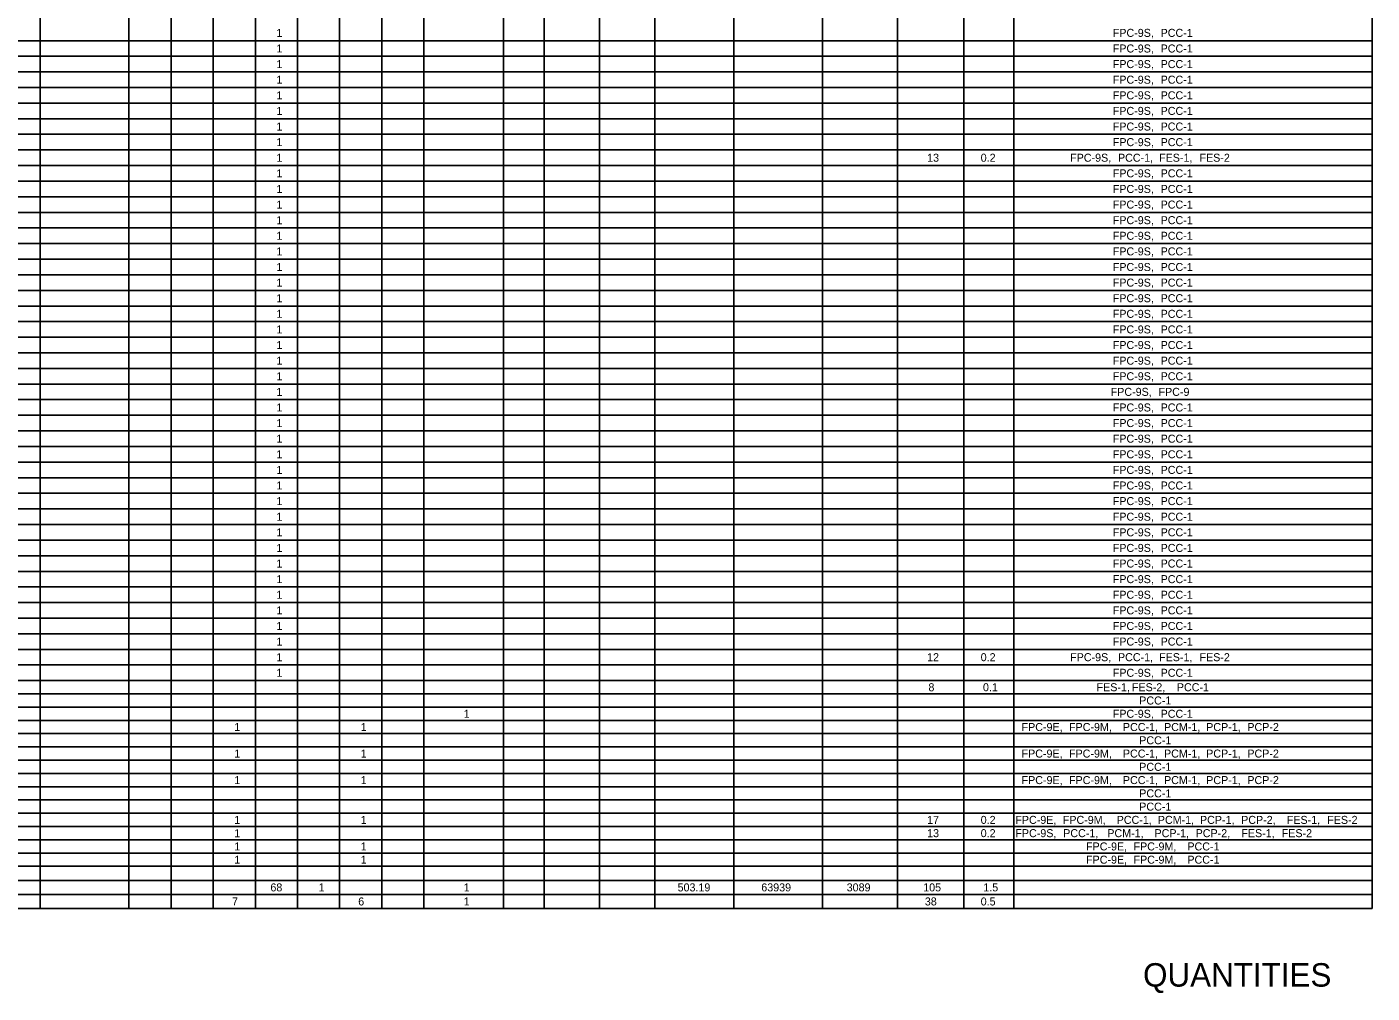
# Model space of a CAD drawing. Extents: x 1226564 to 1228153, y 151309 to 152340.
# Drawn here: x 1227436 to 1228153, y 151309 to 151824 of the extents above; entities that cross this region are included whole.
import ezdxf

# ---------------------------------------------------------------- set-up
doc = ezdxf.new("R2010")
doc.units = 0
doc.layers.add('R_Border Notes', color=7, linetype='Continuous')
doc.layers.add('R_Dimension', color=7, linetype='Continuous')

msp = doc.modelspace()

# ---------------------------------------------------------------- linework, layer by layer
at = {"layer": 'R_Dimension'}
for p, q in [((1227443.42, 151354.44), (1227443.42, 152160.49)), ((1227690.22, 151354.44), (1227690.22, 152160.49)), ((1227770.83, 151354.44), (1227770.83, 152160.49)), ((1227812.79, 151354.44), (1227812.79, 152160.49)), ((1227860.16, 151354.44), (1227860.16, 152160.49)), ((1227900.05, 151354.44), (1227900.05, 152160.49)), ((1227935.36, 151354.44), (1227935.36, 152160.49)), ((1227961.95, 151354.44), (1227961.95, 152160.49)), ((1228152.75, 151354.44), (1228152.75, 152160.49)), ((1227490.79, 151354.44), (1227490.79, 152115.62)), ((1227513.22, 151354.44), (1227513.22, 152115.62)), ((1227535.66, 151354.44), (1227535.66, 152115.62)), ((1227558.1, 151354.44), (1227558.1, 152115.62)), ((1227580.53, 151354.44), (1227580.53, 152115.62)), ((1227602.97, 151354.44), (1227602.97, 152115.62)), ((1227625.41, 151354.44), (1227625.41, 152115.62)), ((1227647.84, 151354.44), (1227647.84, 152115.62)), ((1227711.83, 151354.44), (1227711.83, 152115.62)), ((1227741.33, 151354.44), (1227741.33, 152115.62)), ((1226563.55, 151816.47), (1228152.75, 151816.47)), ((1226563.55, 151808.16), (1228152.75, 151808.16)), ((1226563.55, 151799.85), (1228152.75, 151799.85)), ((1226563.55, 151791.54), (1228152.75, 151791.54)), ((1226563.55, 151783.23), (1228152.75, 151783.23)), ((1226563.55, 151774.92), (1228152.75, 151774.92)), ((1226563.55, 151766.61), (1228152.75, 151766.61)), ((1226563.55, 151758.3), (1228152.75, 151758.3)), ((1226563.55, 151749.99), (1228152.75, 151749.99)), ((1226563.55, 151741.68), (1228152.75, 151741.68)), ((1226563.55, 151733.37), (1228152.75, 151733.37)), ((1226563.55, 151725.06), (1228152.75, 151725.06)), ((1226563.55, 151716.75), (1228152.75, 151716.75)), ((1226563.55, 151708.44), (1228152.75, 151708.44)), ((1226563.55, 151700.13), (1228152.75, 151700.13)), ((1226563.55, 151691.82), (1228152.75, 151691.82)), ((1226563.55, 151683.51), (1228152.75, 151683.51)), ((1226563.55, 151675.2), (1228152.75, 151675.2)), ((1226563.55, 151666.89), (1228152.75, 151666.89)), ((1226563.55, 151658.58), (1228152.75, 151658.58)), ((1226563.55, 151650.27), (1228152.75, 151650.27)), ((1226563.55, 151641.96), (1228152.75, 151641.96)), ((1226563.55, 151633.65), (1228152.75, 151633.65)), ((1226563.55, 151625.34), (1228152.75, 151625.34)), ((1226563.55, 151617.03), (1228152.75, 151617.03)), ((1226563.55, 151608.72), (1228152.75, 151608.72)), ((1226563.55, 151600.41), (1228152.75, 151600.41)), ((1226563.55, 151592.1), (1228152.75, 151592.1)), ((1226563.55, 151583.79), (1228152.75, 151583.79)), ((1226563.55, 151575.48), (1228152.75, 151575.48)), ((1226563.55, 151567.17), (1228152.75, 151567.17)), ((1226563.55, 151558.86), (1228152.75, 151558.86)), ((1226563.55, 151550.55), (1228152.75, 151550.55)), ((1226563.55, 151542.24), (1228152.75, 151542.24)), ((1226563.55, 151533.93), (1228152.75, 151533.93)), ((1226563.55, 151525.62), (1228152.75, 151525.62)), ((1226563.55, 151517.31), (1228152.75, 151517.31)), ((1226563.55, 151509), (1228152.75, 151509)), ((1226563.55, 151500.69), (1228152.75, 151500.69)), ((1226563.55, 151492.38), (1228152.75, 151492.38)), ((1226563.55, 151484.07), (1228152.75, 151484.07)), ((1226563.55, 151475.76), (1228152.75, 151475.76)), ((1226563.55, 151468.7), (1228152.75, 151468.7)), ((1226563.55, 151461.64), (1228152.75, 151461.64)), ((1226563.55, 151454.57), (1228152.75, 151454.57)), ((1226563.55, 151447.51), (1228152.75, 151447.51)), ((1226563.55, 151440.45), (1228152.75, 151440.45)), ((1226563.55, 151433.38), (1228152.75, 151433.38)), ((1226563.55, 151426.32), (1228152.75, 151426.32)), ((1226563.55, 151419.26), (1228152.75, 151419.26)), ((1226563.55, 151412.19), (1228152.75, 151412.19)), ((1226563.55, 151405.13), (1228152.75, 151405.13)), ((1226563.55, 151398.07), (1228152.75, 151398.07)), ((1226563.55, 151391), (1228152.75, 151391)), ((1226563.55, 151383.94), (1228152.75, 151383.94)), ((1226563.55, 151376.88), (1228152.75, 151376.88)), ((1226563.55, 151369.4), (1228152.75, 151369.4)), ((1226563.55, 151361.92), (1228152.75, 151361.92)), ((1226563.55, 151354.44), (1228152.75, 151354.44))]:
    msp.add_line(p, q, dxfattribs=at)

# ---------------------------------------------------------------- texts
at = {"layer": 'R_Border Notes'}
msp.add_text('QUANTITIES', height=12.5, dxfattribs=at).set_placement((1228030.78, 151312.82))
at = {"layer": 'R_Dimension'}
for s, height, p in [('1', 4.26, (1227569.31, 151818.49)), ('FPC-9S,', 4.261, (1228014.67, 151818.49)), (' PCC-1', 4.261, (1228038.56, 151818.49)), ('1', 4.26, (1227569.31, 151810.18)), ('FPC-9S,', 4.261, (1228014.67, 151810.18)), (' PCC-1', 4.261, (1228038.56, 151810.18)), ('1', 4.26, (1227569.31, 151801.87)), ('FPC-9S,', 4.261, (1228014.67, 151801.87)), (' PCC-1', 4.261, (1228038.56, 151801.87)), ('1', 4.26, (1227569.31, 151793.56)), ('FPC-9S,', 4.261, (1228014.67, 151793.56)), (' PCC-1', 4.261, (1228038.56, 151793.56)), ('1', 4.26, (1227569.31, 151785.25)), ('FPC-9S,', 4.261, (1228014.67, 151785.25)), (' PCC-1', 4.261, (1228038.56, 151785.25)), ('1', 4.26, (1227569.31, 151776.94)), ('FPC-9S,', 4.261, (1228014.67, 151776.94)), (' PCC-1', 4.261, (1228038.56, 151776.94)), ('1', 4.26, (1227569.31, 151768.63)), ('FPC-9S,', 4.261, (1228014.67, 151768.63)), (' PCC-1', 4.261, (1228038.56, 151768.63)), ('1', 4.26, (1227569.31, 151760.32)), ('FPC-9S,', 4.261, (1228014.67, 151760.32)), (' PCC-1', 4.261, (1228038.56, 151760.32)), ('1', 4.26, (1227569.31, 151752.01)), ('13', 4.261, (1227915.79, 151752.01)), ('0.2', 4.261, (1227944.33, 151752.01)), ('FPC-9S,', 4.261, (1227991.96, 151752.01)), (' PCC-1,', 4.261, (1228015.85, 151752.01)), (' FES-1,', 4.261, (1228037.76, 151752.01)), (' FES-2', 4.261, (1228059.27, 151752.01)), ('1', 4.26, (1227569.31, 151743.7)), ('FPC-9S,', 4.261, (1228014.67, 151743.7)), (' PCC-1', 4.261, (1228038.56, 151743.7)), ('1', 4.26, (1227569.31, 151735.39)), ('FPC-9S,', 4.261, (1228014.67, 151735.39)), (' PCC-1', 4.261, (1228038.56, 151735.39)), ('1', 4.26, (1227569.31, 151727.08)), ('FPC-9S,', 4.261, (1228014.67, 151727.08)), (' PCC-1', 4.261, (1228038.56, 151727.08)), ('1', 4.26, (1227569.31, 151718.77)), ('FPC-9S,', 4.261, (1228014.67, 151718.77)), (' PCC-1', 4.261, (1228038.56, 151718.77)), ('1', 4.26, (1227569.31, 151710.46)), ('FPC-9S,', 4.261, (1228014.67, 151710.46)), (' PCC-1', 4.261, (1228038.56, 151710.46)), ('1', 4.26, (1227569.31, 151702.15)), ('FPC-9S,', 4.261, (1228014.67, 151702.15)), (' PCC-1', 4.261, (1228038.56, 151702.15)), ('1', 4.26, (1227569.31, 151693.84)), ('FPC-9S,', 4.261, (1228014.67, 151693.84)), (' PCC-1', 4.261, (1228038.56, 151693.84)), ('1', 4.26, (1227569.31, 151685.53)), ('FPC-9S,', 4.261, (1228014.67, 151685.53)), (' PCC-1', 4.261, (1228038.56, 151685.53)), ('1', 4.26, (1227569.31, 151677.22)), ('FPC-9S,', 4.261, (1228014.67, 151677.22)), (' PCC-1', 4.261, (1228038.56, 151677.22)), ('1', 4.26, (1227569.31, 151668.91)), ('FPC-9S,', 4.261, (1228014.67, 151668.91)), (' PCC-1', 4.261, (1228038.56, 151668.91)), ('1', 4.26, (1227569.31, 151660.6)), ('FPC-9S,', 4.261, (1228014.67, 151660.6)), (' PCC-1', 4.261, (1228038.56, 151660.6)), ('1', 4.26, (1227569.31, 151652.29)), ('FPC-9S,', 4.261, (1228014.67, 151652.29)), (' PCC-1', 4.261, (1228038.56, 151652.29)), ('1', 4.26, (1227569.31, 151643.98)), ('FPC-9S,', 4.261, (1228014.67, 151643.98)), (' PCC-1', 4.261, (1228038.56, 151643.98)), ('1', 4.26, (1227569.31, 151635.67)), ('FPC-9S,', 4.261, (1228014.67, 151635.67)), (' PCC-1', 4.261, (1228038.56, 151635.67)), ('1', 4.26, (1227569.31, 151627.36)), ('FPC-9S,', 4.261, (1228013.55, 151627.36)), (' FPC-9', 4.261, (1228037.44, 151627.36)), ('1', 4.26, (1227569.31, 151619.05)), ('FPC-9S,', 4.261, (1228014.67, 151619.05)), (' PCC-1', 4.261, (1228038.56, 151619.05)), ('1', 4.26, (1227569.31, 151610.74)), ('FPC-9S,', 4.261, (1228014.67, 151610.74)), (' PCC-1', 4.261, (1228038.56, 151610.74)), ('1', 4.26, (1227569.31, 151602.43)), ('FPC-9S,', 4.261, (1228014.67, 151602.43)), (' PCC-1', 4.261, (1228038.56, 151602.43)), ('1', 4.26, (1227569.31, 151594.12)), ('FPC-9S,', 4.261, (1228014.67, 151594.12)), (' PCC-1', 4.261, (1228038.56, 151594.12)), ('1', 4.26, (1227569.31, 151585.81)), ('FPC-9S,', 4.261, (1228014.67, 151585.81)), (' PCC-1', 4.261, (1228038.56, 151585.81)), ('1', 4.26, (1227569.31, 151577.51)), ('FPC-9S,', 4.261, (1228014.67, 151577.51)), (' PCC-1', 4.261, (1228038.56, 151577.51)), ('FPC-9S,', 4.261, (1228014.67, 151569.2)), (' PCC-1', 4.261, (1228038.56, 151569.2)), ('1', 4.26, (1227569.31, 151569.2)), ('1', 4.26, (1227569.31, 151560.89)), ('FPC-9S,', 4.261, (1228014.67, 151560.89)), (' PCC-1', 4.261, (1228038.56, 151560.89)), ('1', 4.26, (1227569.31, 151552.58)), ('FPC-9S,', 4.261, (1228014.67, 151552.58)), (' PCC-1', 4.261, (1228038.56, 151552.58)), ('1', 4.26, (1227569.31, 151544.27)), ('FPC-9S,', 4.261, (1228014.67, 151544.27)), (' PCC-1', 4.261, (1228038.56, 151544.27)), ('1', 4.26, (1227569.31, 151535.96)), ('FPC-9S,', 4.261, (1228014.67, 151535.96)), (' PCC-1', 4.261, (1228038.56, 151535.96)), ('1', 4.26, (1227569.31, 151527.65)), ('FPC-9S,', 4.261, (1228014.67, 151527.65)), (' PCC-1', 4.261, (1228038.56, 151527.65)), ('1', 4.26, (1227569.31, 151519.34)), ('FPC-9S,', 4.261, (1228014.67, 151519.34)), (' PCC-1', 4.261, (1228038.56, 151519.34)), ('1', 4.26, (1227569.31, 151511.03)), ('FPC-9S,', 4.261, (1228014.67, 151511.03)), (' PCC-1', 4.261, (1228038.56, 151511.03)), ('1', 4.26, (1227569.31, 151502.72)), ('FPC-9S,', 4.261, (1228014.67, 151502.72)), (' PCC-1', 4.261, (1228038.56, 151502.72)), ('1', 4.26, (1227569.31, 151494.41)), ('FPC-9S,', 4.261, (1228014.67, 151494.41)), (' PCC-1', 4.261, (1228038.56, 151494.41)), ('1', 4.26, (1227569.31, 151486.1)), ('12', 4.261, (1227915.79, 151486.1)), ('0.2', 4.261, (1227944.33, 151486.1)), ('FPC-9S,', 4.261, (1227991.96, 151486.1)), (' PCC-1,', 4.261, (1228015.85, 151486.1)), (' FES-1,', 4.261, (1228037.76, 151486.1)), (' FES-2', 4.261, (1228059.27, 151486.1)), ('1', 4.26, (1227569.31, 151477.79)), ('FPC-9S,', 4.261, (1228014.67, 151477.79)), (' PCC-1', 4.261, (1228038.56, 151477.79)), ('8', 4.26, (1227916.5, 151470.1)), ('0.1', 4.261, (1227945.54, 151470.1)), ('FES-1,', 4.261, (1228006.03, 151470.1)), (' FES-2,', 4.261, (1228023.28, 151470.1)), (' PCC-1', 4.261, (1228047.2, 151470.1)), ('PCC-1', 4.261, (1228028.75, 151463.04)), ('1', 4.26, (1227669.03, 151455.97)), ('FPC-9S,', 4.261, (1228014.67, 151455.97)), (' PCC-1', 4.261, (1228038.56, 151455.97)), ('1', 4.26, (1227546.88, 151448.91)), ('1', 4.26, (1227614.19, 151448.91)), ('FPC-9E,', 4.261, (1227966.09, 151448.91)), (' FPC-9M,', 4.261, (1227989.78, 151448.91)), (' PCC-1,', 4.261, (1228018.47, 151448.91)), (' PCM-1,', 4.261, (1228040.38, 151448.91)), (' PCP-1,', 4.261, (1228062.82, 151448.91)), (' PCP-2', 4.261, (1228084.74, 151448.91)), ('PCC-1', 4.261, (1228028.75, 151441.85)), ('1', 4.26, (1227546.88, 151434.78)), ('1', 4.26, (1227614.19, 151434.78)), ('FPC-9E,', 4.261, (1227966.09, 151434.78)), (' FPC-9M,', 4.261, (1227989.78, 151434.78)), (' PCC-1,', 4.261, (1228018.47, 151434.78)), (' PCM-1,', 4.261, (1228040.38, 151434.78)), (' PCP-1,', 4.261, (1228062.82, 151434.78)), (' PCP-2', 4.261, (1228084.74, 151434.78)), ('PCC-1', 4.261, (1228028.75, 151427.72)), ('1', 4.26, (1227546.88, 151420.66)), ('1', 4.26, (1227614.19, 151420.66)), ('FPC-9E,', 4.261, (1227966.09, 151420.66)), (' FPC-9M,', 4.261, (1227989.78, 151420.66)), (' PCC-1,', 4.261, (1228018.47, 151420.66)), (' PCM-1,', 4.261, (1228040.38, 151420.66)), (' PCP-1,', 4.261, (1228062.82, 151420.66)), (' PCP-2', 4.261, (1228084.74, 151420.66)), ('PCC-1', 4.261, (1228028.75, 151413.59)), ('PCC-1', 4.261, (1228028.75, 151406.53)), ('1', 4.26, (1227546.88, 151399.47)), ('1', 4.26, (1227614.19, 151399.47)), ('17', 4.261, (1227915.79, 151399.47)), ('0.2', 4.261, (1227944.33, 151399.47)), ('FPC-9E,', 4.261, (1227962.78, 151399.47)), (' FPC-9M,', 4.261, (1227986.47, 151399.47)), (' PCC-1,', 4.261, (1228015.16, 151399.47)), (' PCM-1,', 4.261, (1228037.07, 151399.47)), (' PCP-1,', 4.261, (1228059.52, 151399.47)), (' PCP-2,', 4.261, (1228081.43, 151399.47)), (' FES-1,', 4.261, (1228105.76, 151399.47)), (' FES-2', 4.261, (1228127.27, 151399.47)), ('1', 4.26, (1227546.88, 151392.4)), ('13', 4.261, (1227915.79, 151392.4)), ('0.2', 4.261, (1227944.33, 151392.4)), ('FPC-9S,', 4.261, (1227962.78, 151392.4)), (' PCC-1,', 4.261, (1227986.68, 151392.4)), ('  PCM-1,', 4.261, (1228008.59, 151392.4)), (' PCP-1,', 4.261, (1228035.3, 151392.4)), (' PCP-2,', 4.261, (1228057.21, 151392.4)), (' FES-1,', 4.261, (1228081.53, 151392.4)), (' FES-2', 4.261, (1228103.04, 151392.4)), ('1', 4.26, (1227546.88, 151385.34)), ('1', 4.26, (1227614.19, 151385.34)), ('FPC-9E,', 4.261, (1228000.43, 151385.34)), (' FPC-9M,', 4.261, (1228024.12, 151385.34)), (' PCC-1', 4.261, (1228052.81, 151385.34)), ('1', 4.26, (1227546.88, 151378.28)), ('1', 4.26, (1227614.19, 151378.28)), ('FPC-9E,', 4.261, (1228000.43, 151378.28)), (' FPC-9M,', 4.261, (1228024.12, 151378.28)), (' PCC-1', 4.261, (1228052.81, 151378.28)), ('68', 4.261, (1227566.09, 151363.53)), ('1', 4.26, (1227591.75, 151363.53)), ('1', 4.26, (1227669.03, 151363.53)), ('503.19', 4.261, (1227782.93, 151363.53)), ('63939', 4.261, (1227827.5, 151363.53)), ('3089', 4.261, (1227872.97, 151363.53)), ('105', 4.261, (1227913.71, 151363.53)), ('1.5', 4.261, (1227945.71, 151363.53)), ('7', 4.26, (1227545.67, 151356.05)), ('6', 4.26, (1227612.86, 151356.05)), ('1', 4.26, (1227669.03, 151356.05)), ('38', 4.261, (1227914.58, 151356.05)), ('0.5', 4.261, (1227944.33, 151356.05))]:
    msp.add_text(s, height=height, dxfattribs=at).set_placement(p)

doc.saveas('drawing.dxf')
